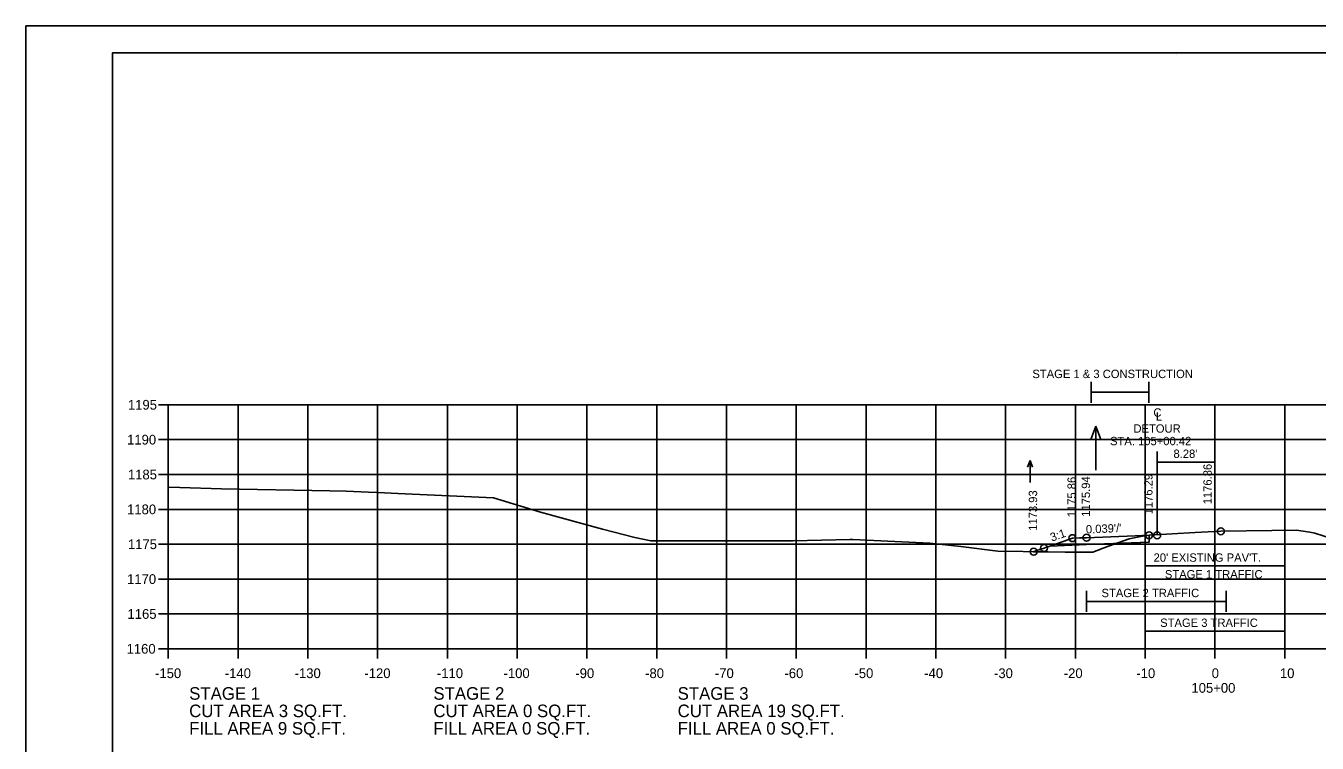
# Model space of a CAD drawing. Extents: x 1368971 to 1374497, y 378717 to 381839.
# Drawn here: x 1370882.3 to 1371067.4, y 378827.5 to 378930.4 of the extents above; entities that cross this region are included whole.
import ezdxf

# ---------------------------------------------------------------- set-up
doc = ezdxf.new("R2010")
doc.units = 0
for name, color, linetype in [('R_Axis', 7, 'Continuous'), ('R_Axis Annot', 7, 'Continuous'), ('R_Border', 7, 'Continuous'), ('R_Contours', 7, 'Continuous'), ('R_Detour', 7, 'Continuous'), ('R_Detour Annot', 7, 'Continuous'), ('R_Dimension', 7, 'Continuous'), ('R_Exist Surface', 7, 'Continuous'), ('R_Grid', 7, 'Continuous'), ('R_No Plot', 7, 'Continuous'), ('R_Water Annot', 7, 'Continuous'), ('R_Xsect Elev', 7, 'Continuous')]:
    doc.layers.add(name, color=color, linetype=linetype)

msp = doc.modelspace()

# ---------------------------------------------------------------- linework, layer by layer
at = {"layer": 'R_Axis'}
for p, q in [((1370901.31, 378876.06), (1370902.71, 378876.06)), ((1370902.71, 378841.06), (1370902.71, 378876.06)), ((1370901.31, 378871.06), (1370902.71, 378871.06)), ((1370901.31, 378866.06), (1370902.71, 378866.06)), ((1370901.31, 378861.06), (1370902.71, 378861.06)), ((1370901.31, 378856.06), (1370902.71, 378856.06)), ((1370901.31, 378851.06), (1370902.71, 378851.06)), ((1370901.31, 378846.06), (1370902.71, 378846.06)), ((1370901.31, 378841.06), (1370902.71, 378841.06)), ((1370902.71, 378841.06), (1371202.71, 378841.06)), ((1370902.71, 378839.66), (1370902.71, 378841.06)), ((1370912.71, 378839.66), (1370912.71, 378841.06)), ((1370922.71, 378839.66), (1370922.71, 378841.06)), ((1370932.71, 378839.66), (1370932.71, 378841.06)), ((1370942.71, 378839.66), (1370942.71, 378841.06)), ((1370952.71, 378839.66), (1370952.71, 378841.06)), ((1370962.71, 378839.66), (1370962.71, 378841.06)), ((1370972.71, 378839.66), (1370972.71, 378841.06)), ((1370982.71, 378839.66), (1370982.71, 378841.06)), ((1370992.71, 378839.66), (1370992.71, 378841.06)), ((1371002.71, 378839.66), (1371002.71, 378841.06)), ((1371012.71, 378839.66), (1371012.71, 378841.06)), ((1371022.71, 378839.66), (1371022.71, 378841.06)), ((1371032.71, 378839.66), (1371032.71, 378841.06)), ((1371042.71, 378839.66), (1371042.71, 378841.06)), ((1371052.71, 378839.66), (1371052.71, 378841.06)), ((1371062.71, 378839.66), (1371062.71, 378841.06))]:
    msp.add_line(p, q, dxfattribs=at)
at = {"layer": 'R_Border'}
for p, q in [((1370894.71, 378926.52), (1371210.89, 378926.52)), ((1370894.71, 378721.06), (1370894.71, 378926.52)), ((1371047.23, 378926.26), (1371047.23, 378926.26)), ((1371047.23, 378926.26), (1371047.23, 378926.26))]:
    msp.add_line(p, q, dxfattribs=at)
at = {"layer": 'R_Contours'}
msp.add_line((1371026.73, 378854.99), (1371028.83, 378854.96), dxfattribs=at)
for points in [[(1371043.27, 378857.35), (1371041.27, 378857.27), (1371034.31, 378857), (1371033.28, 378856.96), (1371032.28, 378856.93), (1371030.96, 378856.46), (1371029.05, 378855.8), (1371028.49, 378855.6), (1371028.23, 378855.51), (1371027.15, 378855.14), (1371026.73, 378854.99)], [(1371028.83, 378854.96), (1371031.25, 378854.94), (1371031.65, 378854.93), (1371035.19, 378854.93), (1371037.31, 378855.74), (1371040.4, 378856.82), (1371042.09, 378857.16), (1371043.27, 378857.35)], [(1371026.73, 378854.99), (1371026.73, 378854.99)]]:
    msp.add_lwpolyline(points, dxfattribs=at)
for points in [[(1371038.54, 378856.17), (1371040.4, 378856.82), (1371042.09, 378857.16), (1371043.27, 378857.35), (1371043.27, 378856.35)], [(1371026.73, 378854.99), (1371026.73, 378854.99), (1371028.83, 378854.96), (1371031.25, 378854.94), (1371031.65, 378854.93), (1371035.19, 378854.93), (1371037.31, 378855.74), (1371038.54, 378856.17), (1371034.31, 378856), (1371029.05, 378855.8), (1371028.49, 378855.6), (1371028.23, 378855.51), (1371027.15, 378855.14)]]:
    msp.add_lwpolyline(points, close=True, dxfattribs=at)
at = {"layer": 'R_Detour'}
for points in [[(1371026.73, 378854.99), (1371027.15, 378855.14), (1371028.23, 378855.51), (1371028.49, 378855.6), (1371029.05, 378855.8), (1371030.96, 378856.46), (1371032.28, 378856.93), (1371033.28, 378856.96), (1371034.31, 378857), (1371041.27, 378857.27), (1371043.27, 378857.35)], [(1371043.27, 378857.35), (1371043.27, 378856.35), (1371034.31, 378856), (1371029.05, 378855.8)]]:
    msp.add_lwpolyline(points, dxfattribs=at)
at = {"layer": 'R_Dimension'}
for p, q in [((1371034.98, 378876.36), (1371034.98, 378879.36)), ((1371034.98, 378877.86), (1371043.25, 378877.86)), ((1371043.25, 378876.36), (1371043.25, 378879.36)), ((1371044.43, 378857.42), (1371044.43, 378869.35)), ((1371052.71, 378867.3), (1371052.71, 378869.35)), ((1371042.71, 378851.45), (1371042.71, 378854.45)), ((1371062.71, 378851.45), (1371062.71, 378854.45)), ((1371042.71, 378852.95), (1371062.71, 378852.95)), ((1371034.31, 378846.37), (1371034.31, 378849.37)), ((1371054.31, 378846.37), (1371054.31, 378849.37)), ((1371034.31, 378847.87), (1371054.31, 378847.87)), ((1371042.71, 378842.1), (1371042.71, 378845.1)), ((1371062.71, 378842.1), (1371062.71, 378845.1)), ((1371042.71, 378843.6), (1371062.71, 378843.6))]:
    msp.add_line(p, q, dxfattribs=at)
msp.add_lwpolyline([(1371044.43, 378867.85), (1371052.71, 378867.85)], dxfattribs=at)
at = {"layer": 'R_Exist Surface'}
msp.add_lwpolyline([(1370902.71, 378864.26), (1370904.38, 378864.2), (1370910.33, 378864.02), (1370925.87, 378863.73), (1370928.19, 378863.66), (1370931.43, 378863.53), (1370932.75, 378863.5), (1370935.6, 378863.35), (1370949.32, 378862.71), (1370956.06, 378860.64), (1370964.94, 378858.2), (1370969.58, 378857.01), (1370971.89, 378856.56), (1370976.53, 378856.53), (1370992.25, 378856.54), (1371000.4, 378856.73), (1371000.8, 378856.72), (1371011.86, 378856.21), (1371016.31, 378855.72), (1371021.62, 378855.05), (1371028.83, 378854.96), (1371031.25, 378854.94), (1371031.65, 378854.93), (1371035.19, 378854.93), (1371037.31, 378855.74), (1371040.4, 378856.82), (1371042.09, 378857.16), (1371043.27, 378857.35), (1371049.9, 378857.73), (1371053.56, 378857.92), (1371060.86, 378858.03), (1371064.38, 378858.08), (1371066.33, 378857.77), (1371067.05, 378857.67), (1371069.43, 378856.86)], dxfattribs=at)
at = {"layer": 'R_Grid'}
for p, q in [((1370902.71, 378876.06), (1371202.71, 378876.06)), ((1370902.71, 378841.06), (1370902.71, 378876.06)), ((1370912.71, 378841.06), (1370912.71, 378876.06)), ((1370922.71, 378841.06), (1370922.71, 378876.06)), ((1370932.71, 378841.06), (1370932.71, 378876.06)), ((1370942.71, 378841.06), (1370942.71, 378876.06)), ((1370952.71, 378841.06), (1370952.71, 378876.06)), ((1370962.71, 378841.06), (1370962.71, 378876.06)), ((1370972.71, 378841.06), (1370972.71, 378876.06)), ((1370982.71, 378841.06), (1370982.71, 378876.06)), ((1370992.71, 378841.06), (1370992.71, 378876.06)), ((1371002.71, 378841.06), (1371002.71, 378876.06)), ((1371012.71, 378841.06), (1371012.71, 378876.06)), ((1371022.71, 378841.06), (1371022.71, 378876.06)), ((1371032.71, 378841.06), (1371032.71, 378876.06)), ((1371042.71, 378841.06), (1371042.71, 378876.06)), ((1371052.71, 378841.06), (1371052.71, 378876.06)), ((1371062.71, 378841.06), (1371062.71, 378876.06)), ((1370902.71, 378871.06), (1371202.71, 378871.06)), ((1370902.71, 378866.06), (1371202.71, 378866.06)), ((1370902.71, 378861.06), (1371202.71, 378861.06)), ((1370902.71, 378856.06), (1371202.71, 378856.06)), ((1370902.71, 378851.06), (1371202.71, 378851.06)), ((1370902.71, 378846.06), (1371202.71, 378846.06)), ((1370902.71, 378841.06), (1371202.71, 378841.06))]:
    msp.add_line(p, q, dxfattribs=at)
at = {"layer": 'R_No Plot'}
msp.add_line((1370882.31, 378930.42), (1371215.64, 378930.42), dxfattribs=at)
for points in [[(1370882.3, 378930.42), (1371215.64, 378930.42), (1371215.64, 378717.08), (1370882.3, 378717.08)], [(1371128.63, 378926.52), (1371128.63, 378916.64), (1371164.36, 378916.64), (1371164.36, 378913.72), (1371187.56, 378913.72), (1371187.56, 378889.39), (1371210.89, 378889.39), (1371210.89, 378721.06), (1370894.71, 378721.06), (1370894.71, 378926.52)]]:
    msp.add_lwpolyline(points, close=True, dxfattribs=at)
for centre in [(1371032.28, 378856.93), (1371032.28, 378856.93), (1371034.31, 378857), (1371034.31, 378857), (1371043.27, 378857.35), (1371043.27, 378857.35), (1371044.43, 378857.32), (1371044.43, 378857.32), (1371053.56, 378857.92), (1371026.73, 378854.99), (1371026.73, 378854.99), (1371028.23, 378855.51), (1371028.23, 378855.51)]:
    msp.add_circle(centre, 0.5, dxfattribs=at)
at = {"layer": 'R_Water Annot'}
for p, q in [((1371035.64, 378872.98), (1371034.94, 378871.06)), ((1371035.64, 378866.7), (1371035.64, 378872.98)), ((1371035.64, 378872.98), (1371036.34, 378871.06)), ((1371026.21, 378868.07), (1371025.86, 378867.11)), ((1371026.21, 378864.93), (1371026.21, 378868.07)), ((1371026.21, 378868.07), (1371026.56, 378867.11))]:
    msp.add_line(p, q, dxfattribs=at)

# ---------------------------------------------------------------- texts
at = {"layer": 'R_Axis'}
msp.add_text('-', height=0.0001, dxfattribs=at).set_placement((1370902.71, 378841.06))
at = {"layer": 'R_Axis Annot'}
for s, height, p in [('1195', 1.4, (1370896.93, 378875.36)), ('1190', 1.4, (1370896.81, 378870.36)), ('1185', 1.4, (1370896.93, 378865.36)), ('1180', 1.4, (1370896.81, 378860.36)), ('1175', 1.4, (1370896.93, 378855.36)), ('1170', 1.4, (1370896.81, 378850.36)), ('1165', 1.4, (1370896.87, 378845.36)), ('1160', 1.4, (1370896.74, 378840.36)), ('-150', 1.4, (1370900.82, 378836.86)), ('-140', 1.4, (1370910.82, 378836.86)), ('-130', 1.4, (1370920.82, 378836.86)), ('-120', 1.4, (1370930.82, 378836.86)), ('-110', 1.4, (1370941.21, 378836.86)), ('-100', 1.4, (1370950.76, 378836.86)), ('-90', 1.4, (1370961.05, 378836.86)), ('-80', 1.4, (1370971.05, 378836.86)), ('-70', 1.4, (1370981.05, 378836.86)), ('-60', 1.4, (1370991.02, 378836.86)), ('-50', 1.4, (1371001.05, 378836.86)), ('-40', 1.4, (1371011.05, 378836.86)), ('-30', 1.4, (1371021.05, 378836.86)), ('-20', 1.4, (1371031.05, 378836.86)), ('-10', 1.4, (1371041.45, 378836.86)), ('0', 1.4, (1371052.25, 378836.86)), ('10', 1.4, (1371062.02, 378836.86)), ('STAGE 1', 1.8, (1370905.71, 378833.76)), ('STAGE 2', 1.8, (1370940.71, 378833.76)), ('STAGE 3', 1.8, (1370975.71, 378833.76)), ('105+00', 1.4, (1371049.34, 378834.76)), ('CUT AREA 3 SQ.FT.', 1.8, (1370905.71, 378831.26)), ('CUT AREA 0 SQ.FT.', 1.8, (1370940.71, 378831.26)), ('CUT AREA 19 SQ.FT.', 1.8, (1370975.71, 378831.26)), ('FILL AREA 9 SQ.FT.', 1.8, (1370905.71, 378828.76)), ('FILL AREA 0 SQ.FT.', 1.8, (1370940.71, 378828.76)), ('FILL AREA 0 SQ.FT.', 1.8, (1370975.71, 378828.76))]:
    msp.add_text(s, height=height, dxfattribs=at).set_placement(p)
at = {"layer": 'R_Detour Annot'}
for s, rotation, p in [('1175.86', 90, (1371032.78, 378859.93)), ('1175.94', 90, (1371034.81, 378860)), ('1176.29', 90, (1371043.77, 378860.35)), ('1173.93', 90, (1371027.23, 378857.99)), ("0.039'/'", 2.2186, (1371034.24, 378857.6)), ('3:1', 19.2262, (1371029.34, 378856.43))]:
    msp.add_text(s, height=1.2, rotation=rotation, dxfattribs=at).set_placement(p)
at = {"layer": 'R_Dimension'}
for s, p in [('STAGE 1 & 3 CONSTRUCTION', (1371026.55, 378879.89)), ('C', (1371043.89, 378874.35)), ('L', (1371044.25, 378873.79)), ('DETOUR', (1371041.03, 378872.06)), ('STA. 105+00.42', (1371037.68, 378870.26)), ("8.28'", (1371046.77, 378868.44)), ("20' EXISTING PAV'T.", (1371043.92, 378853.55)), ('STAGE 1 TRAFFIC', (1371045.54, 378851.15)), ('STAGE 2 TRAFFIC', (1371036.46, 378848.47)), ('STAGE 3 TRAFFIC', (1371044.86, 378844.2))]:
    msp.add_text(s, height=1.2, dxfattribs=at).set_placement(p)
at = {"layer": 'R_Xsect Elev'}
msp.add_text('1176.86', height=1.2, rotation=90, dxfattribs=at).set_placement((1371052.25, 378861.79))

doc.saveas('drawing.dxf')
